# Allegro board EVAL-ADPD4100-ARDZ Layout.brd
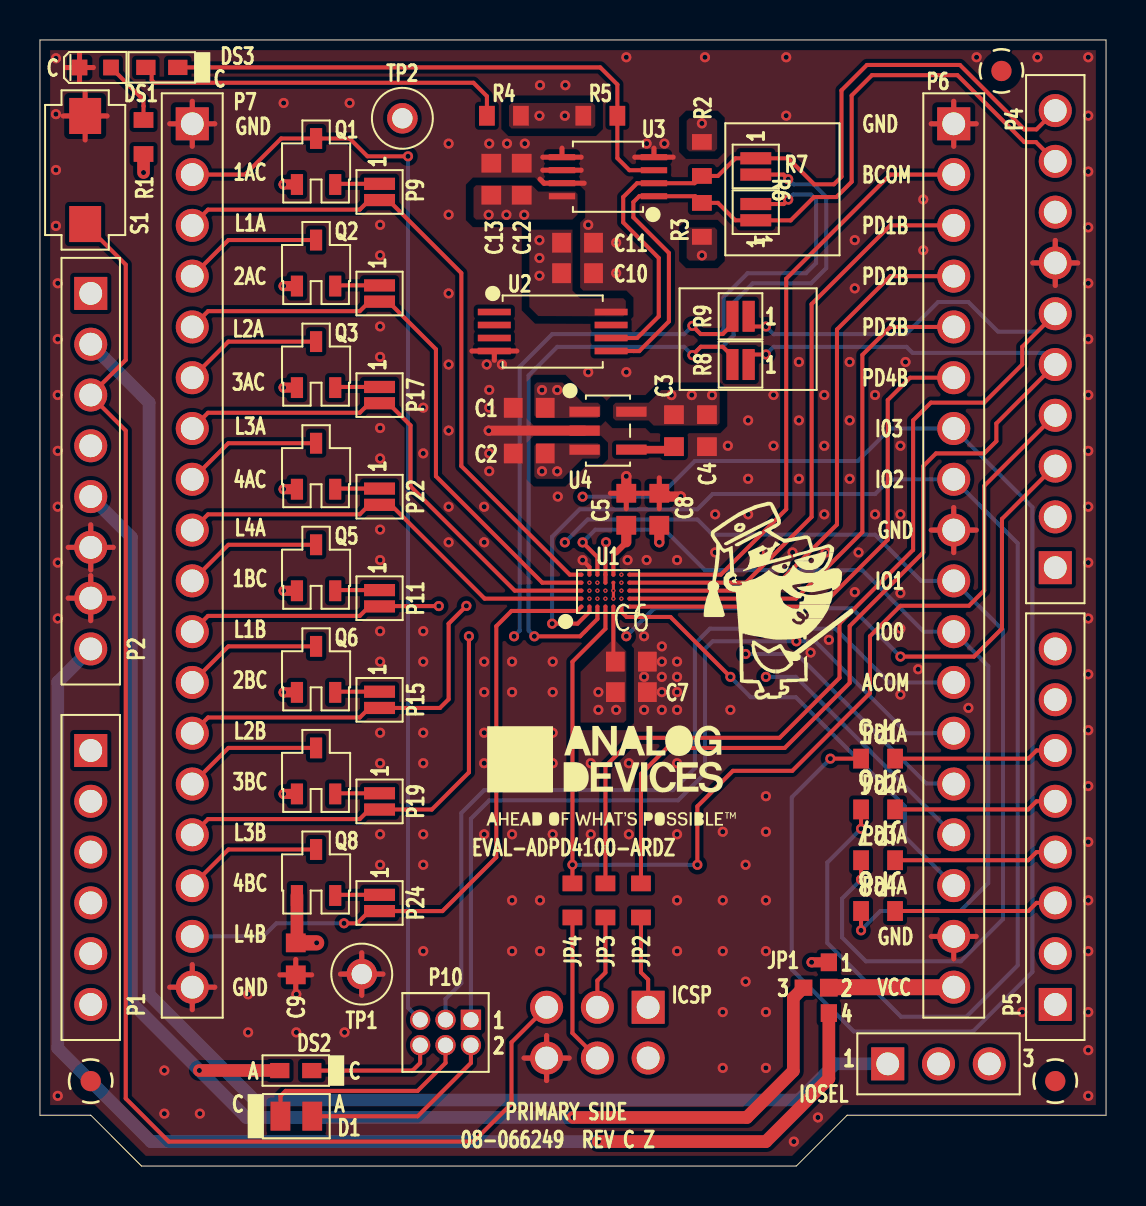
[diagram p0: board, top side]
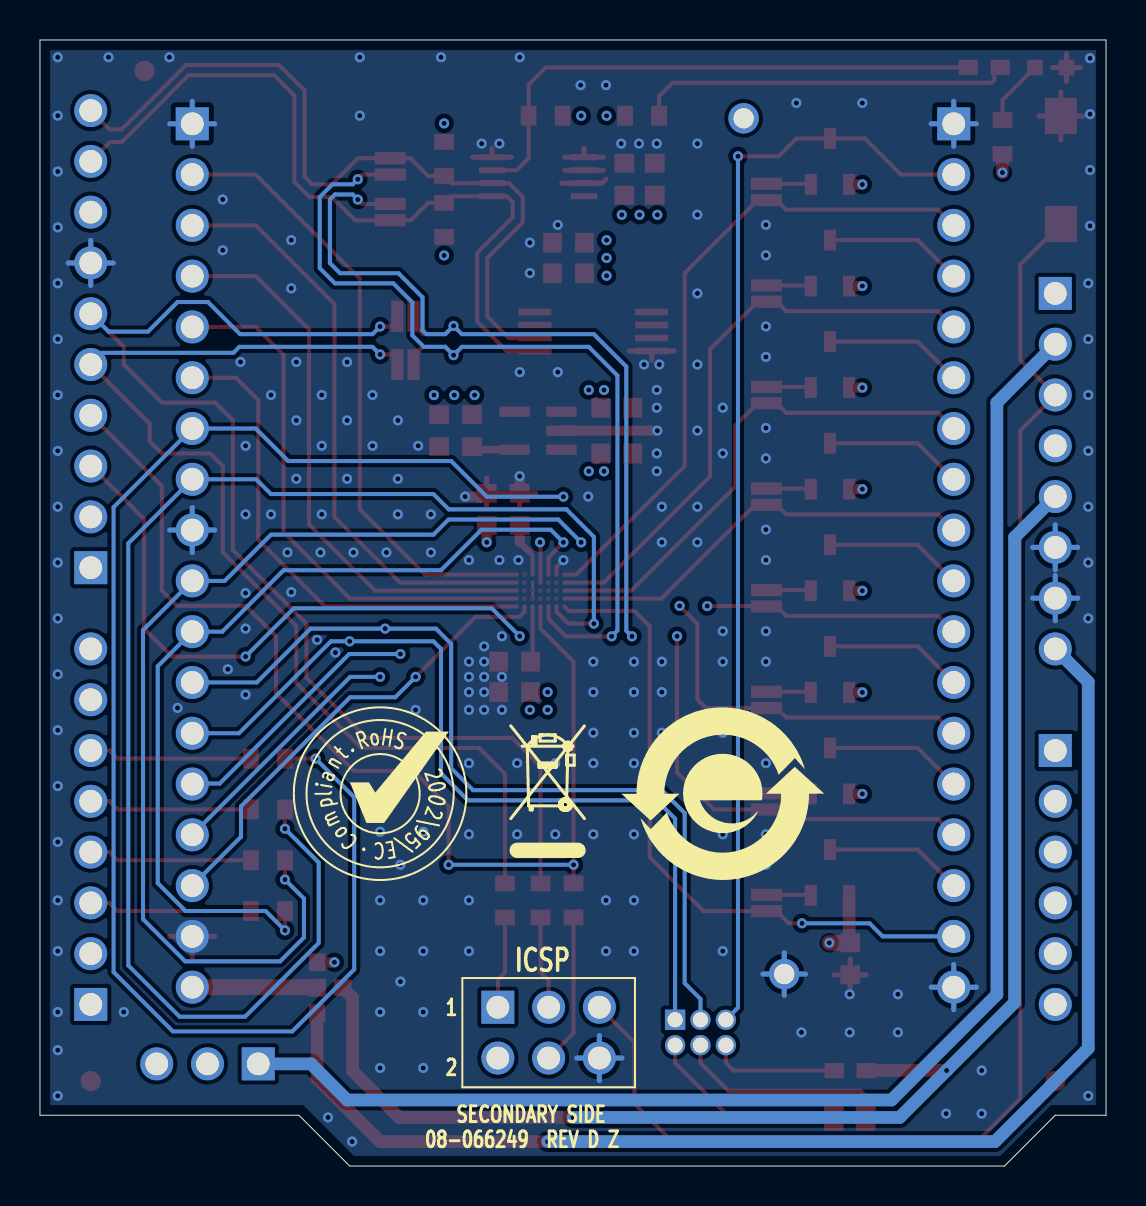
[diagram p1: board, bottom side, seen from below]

Outline 53.34 x 56.31 mm; copper layers: TOP, L2_GND, L3_PWR, BOTTOM. Coordinates in mm from the lower left corner of the outline.
Outline path: 0,56.31 0,2.54 2.54,2.54 5.08,0 37.85,0 40.39,2.54 53.34,2.54 53.34,56.31 0,56.31

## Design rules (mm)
constraint set DEFAULT: min track width 0.203

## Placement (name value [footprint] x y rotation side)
C1  0.1uF  [C0603]  24.48 37.92 180 top
C2  4.7uF  [C0603]  24.48 35.63 180 top
C3  0.01uF  [C0603]  31.72 36.78 90 top
C4  10uF  [C0603]  33.37 36.78 270 top
C5  1uF  [C0603]  29.34 32.84 90 top
C6  0.1uF  [C0603]  29.59 25.22 0 top
C7  4.7uF  [C0603]  29.59 23.7 0 top
C8  0.1uF  [C0603]  30.99 32.84 90 top
C9  4.7uF  [C0603]  12.8 10.36 270 top
C10  0.1uF  [C0603]  26.9 44.65 0 top
C11  4.7uF  [C0603]  26.9 46.17 0 top
C12  0.1uF  [C0603]  24.1 49.35 90 top
C13  4.7uF  [C0603]  22.58 49.35 90 top
D1  VEMD1060X01  [D0805_A]  12.83 2.49 0 top
DS1  SML-LX0603GW-TR  [LED0603-2]  2.77 54.94 0 top
DS2  TLMS1100-GS08  [LED0603]  12.8 4.77 180 top
DS3  TLMS1100-GS08  [LED0603]  6.1 54.94 180 top
IOSEL  TSW-103-08-T-S  [CNTHMHDR1X3L300W100H343]  42.42 5.11 0 top
JP1  4PIN_JUMPER  [4PINJUMPER_0402]  39.47 8.92 0 top
JP2  0  [R0603]  30.07 13.28 90 top
JP3  0  [R0603]  28.29 13.28 90 top
JP4  0  [R0603]  26.64 13.28 90 top
JP5  0  [R0603]  41.93 20.37 0 top
JP6  0  [R0603]  41.93 17.83 0 top
JP7  0  [R0603]  41.93 15.29 0 top
JP8  0  [R0603]  41.93 12.75 0 top
NOREF  -  []  0 2.54 0 top
NOREF#2  -  []  -47.84 -67.68 0 top
NOREF#3  -  []  0 56.31 0 top
NOREF#4  -  []  26.67 67.77 0 top
NOREF#5  -  []  94.36 104.39 0 top
NOREF#6  -  []  53.34 56.31 180 top
NOREF#7  -  []  0 56.31 0 top
NOREF#8  -  []  37.85 0 90 top
NOREF#9  -  []  53.34 2.54 90 top
NOREF#10  -  [unnamed#2]  2.54 4.24 0 top
NOREF#11  -  []  -35.58 -101.92 0 top
NOREF#12  -  []  0 56.31 270 top
NOREF#13  -  []  28.29 19.49 0 top
NOREF#14  -  []  2.54 43.64 270 top
NOREF#15  -  []  53.34 2.54 0 top
NOREF#16  -  [unnamed#2]  48.11 54.77 0 top
NOREF#17  -  []  0 2.54 0 top
NOREF#18  -  []  -25.68 -63.3 0 top
NOREF#19  -  []  44.24 305.7 0 top
NOREF#20  -  []  2.54 2.54 0 top
NOREF#21  -  [unnamed#2]  50.8 4.24 0 top
NOREF#22  -  []  40.39 2.54 0 top
NOREF#23  -  []  37.85 0 0 top
NOREF#24  -  []  -35.58 -101.92 0 top
NOREF#25  -  []  91.44 97.28 0 top
NOREF#26  -  []  5.08 0 0 top
NOREF#27  -  []  -35.58 -101.92 0 top
NOREF#28  -  []  -38.35 -57.07 0 top
NOREF#29  -  []  36.96 28.27 0 top
NOREF#30  -  []  -7.16 231.15 0 top
NOREF#31  -  []  28.14 15.47 180 bottom
NOREF#32  -  []  36.32 18.62 180 bottom
NOREF#33  -  []  19.18 18.62 180 bottom
P1  SSQ-106-03-T-S  [CNSAMTECSSQ-106-XX-X-S]  2.54 20.78 270 top
P2  SSQ-108-03-T-S  [CNSAMTECSSQ-108-XX-X-S]  2.54 43.64 270 top
P3  SSQ-103-03-T-D  [CNSAMTECSSQ-103-XX-X-D]  30.43 7.94 180 bottom
P4  SSQ-110-03-T-S  [CNSAMTECSSQ-110-XX-X-S]  50.8 29.92 90 top
P5  SSQ-108-03-T-S  [CNSAMTECSSQ-108-XX-X-S]  50.8 8.08 90 top
P6  TSW-118-16-G-S  [CNHDR1X18H420]  45.72 52.12 270 top
P7  TSW-118-16-G-S  [CNHDR1X18H420]  7.62 52.12 270 top
P9  -  [JPSLD02]  16.99 48.71 270 top
P10  FTS-103-01-F-D  [CNTHMHDR2X3L150W135H164]  21.56 7.31 180 top
P11  -  [JPSLD02]  16.99 28.39 270 top
P13  -  [JPSLD02]  16.99 43.63 270 top
P15  -  [JPSLD02]  16.99 23.31 270 top
P17  -  [JPSLD02]  16.99 38.55 270 top
P19  -  [JPSLD02]  16.99 18.23 270 top
P22  -  [JPSLD02]  16.99 33.47 270 top
P24  -  [JPSLD02]  16.99 13.15 270 top
Q1  MMBT2222A-TP  [SOT23_B]  13.82 50.24 0 top
Q2  MMBT2222A-TP  [SOT23_B]  13.82 45.16 0 top
Q3  MMBT2222A-TP  [SOT23_B]  13.82 40.08 0 top
Q4  MMBT2222A-TP  [SOT23_B]  13.82 35 0 top
Q5  MMBT2222A-TP  [SOT23_B]  13.82 29.92 0 top
Q6  MMBT2222A-TP  [SOT23_B]  13.82 24.84 0 top
Q7  MMBT2222A-TP  [SOT23_B]  13.82 19.76 0 top
Q8  MMBT2222A-TP  [SOT23_B]  13.82 14.68 0 top
R1  330  [R0603]  5.18 51.46 270 top
R2  10K  [R0603]  33.12 50.37 270 top
R3  10K  [R0603]  33.12 47.32 90 top
R4  330  [R0603]  23.21 52.52 0 top
R5  10K  [R0603]  28.04 52.52 0 top
R6  -  [JPSLD02]  35.81 47.7 90 top
R7  -  [JPSLD02]  35.81 49.99 270 top
R8  -  [JPSLD02]  35.05 40.08 180 top
R9  -  [JPSLD02]  35.05 42.5 180 top
S1  SKQMBBE010  [SWSML236W138H197]  2.26 49.81 270 top
TP1  WHT  [CNKEY5001TP]  16.1 9.6 0 top
TP2  WHT  [CNKEY5001TP]  18.13 52.4 0 top
U1  ADPD4100BCBZR7  [WLCSP35]  28.42 28.73 0 top
U2  M24C16-RDW6TP  [TSSOP8]  25.65 41.73 270 top
U3  ADT75BRMZ  [MSOP8]  28.42 49.48 90 top
U4  LT1761ES5-1.8#TRPBF  [TSOT-5]  28.42 36.78 270 top

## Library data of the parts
C1 C6 C8 C10 C12 = CAP: User Part Number: UPN; Tolerance: 10; alternate symbols: (C0603L); part number: CAP_SM-0.1UF,16V,10,E022365,C0603; tolerance: 10
C2 C7 C9 C11 C13 = CAP: User Part Number: UPN; Tolerance: 10; alternate symbols: (C0603L); part number: CAP_SM-4.7UF,25V,10,E035948,C0603; tolerance: 10
C3 = CAP: User Part Number: UPN; Tolerance: 10; alternate symbols: (C0603L); part number: CAP_SM-0.01UF,50V,10,E018587,C0603; tolerance: 10
C4 = CAP: User Part Number: UPN; Tolerance: 20; alternate symbols: (C0603L); part number: CAP_SM-10UF,10V,20,E022682,C0603; tolerance: 20
C5 = CAP: User Part Number: UPN; Tolerance: 10; alternate symbols: (C0603L); part number: CAP_SM-1UF,25V,10,E034292,C0603; tolerance: 10
D1 = DIOPHOTO: User Part Number: UPN; Tolerance: N/A; alternate symbols: (); part number: DIOPHOTO_SM-VEMD1060X01,20V,N/A,E049449,D0805_A; tolerance: N/A
DS1 = DIOLED: Tolerance: N/A; User Part Number: UPN; alternate symbols: (); part number: DIOLED_SM-SML-LX0603GW-TR,N/A,N/A,E018702,LED0603-2; tolerance: N/A
DS2 DS3 = DIOLED: Tolerance: N/A; User Part Number: UPN; alternate symbols: (); part number: DIOLED_SM-TLMS1100-GS08,N/A,N/A,E015386,LED0603; tolerance: N/A
IOSEL = CN3P: User Part Number: UPN; Tolerance: N/A; alternate symbols: (); part number: CN3P_TH-TSW-103-08-T-S,E031365,CNTHMHDR1X3L300W100H343; tolerance: N/A
JP1 = NC4P_JMPR: Tolerance: N/A; User Part Number: UPN; alternate symbols: (); part number: NC4P_JMPR_SM-4PIN_JUMPER,E006496,4PINJUMPER_0402; tolerance: N/A
JP2-JP8 = RESJMPRSHRT: User Part Number: UPN; Tolerance: JUMPER; alternate symbols: (R0603L); part number: RESJMPRSHRT_SM-0,E004447,1/10W,JUMPER,R0603; tolerance: JUMPER
P1 = CN6P: User Part Number: UPN; Tolerance: N/A; alternate symbols: (); part number: CN6P_TH-SSQ-106-03-T-S,E027150,CNSAMTECSSQ-106-XX-X-S; tolerance: N/A
P2 P5 = CN8P_A: User Part Number: UPN; Tolerance: N/A; alternate symbols: (); part number: CN8P_A_TH-SSQ-108-03-T-S,E027149,CNSAMTECSSQ-108-XX-X-S; tolerance: N/A
P3 = CN6P: User Part Number: UPN; Tolerance: N/A; alternate symbols: (); part number: CN6P_TH-SSQ-103-03-T-D,E027152,CNSAMTECSSQ-103-XX-X-D; tolerance: N/A
P4 = CN10P: User Part Number: UPN; Tolerance: N/A; alternate symbols: (); part number: CN10P_TH-SSQ-110-03-T-S,E027151,CNSAMTECSSQ-110-XX-X-S; tolerance: N/A
P6 P7 = CN18P: User Part Number: UPN; Tolerance: N/A; alternate symbols: (); part number: CN18P_TH-TSW-118-16-G-S,E017097,CNHDR1X18H420; tolerance: N/A
P9 P11 P13 P15 P17 P19 P22 P24 R6-R9 = NC2P: User Part Number: UPN; Tolerance: N/A; alternate symbols: (); part number: NC2P_SM-JPSLD02,E006230,JPSLD02; tolerance: N/A
P10 = CN6P_ODD_EVEN: User Part Number: UPN; Tolerance: N/A; alternate symbols: (); part number: CN6P_ODD_EVEN_TH-FTS-103-01-F-D,E047281,CNTHMHDR2X3L150W135H164; tolerance: N/A
Q1-Q8 = TRANNPN_V2: User Part Number: UPN; Tolerance: N/A; alternate symbols: (); part number: TRANNPN_V2_SM-MMBT2222A-TP,E035724,SOT23_B; tolerance: N/A
R1 R4 = RES: User Part Number: UPN; Tolerance: 5; alternate symbols: (R0603L); part number: RES_SM-330,E003857,1/10W,5,R0603; tolerance: 5
R2 R3 R5 = RES: User Part Number: UPN; Tolerance: 5; alternate symbols: (R0603L); part number: RES_SM-10K,E042780,1/10W,5,R0603; tolerance: 5
S1 = SWSPST2PIN_V3: Tolerance: N/A; User Part Number: UPN; alternate symbols: (); part number: SWSPST2PIN_V3_SM-SKQMBBE010,E026439,SWSML236W138H197; tolerance: N/A
TP1 TP2 = CNTP1P: Tolerance: N/A; User Part Number: UPN; alternate symbols: (); part number: CNTP1P_TH-WHT,E006153,CNKEY5001TP; tolerance: N/A
U1 = ADPD4100: Tolerance: N/A; User Part Number: UPN; alternate symbols: (); part number: ADPD4100_SM-ADPD4100BCBZR7,E041910,WLCSP35; tolerance: N/A
U2 = ICM24CXX_V2: Tolerance: N/A; User Part Number: UPN; alternate symbols: (); part number: ICM24CXX_V2_SM-M24C16-RDW6TP,E026352,TSSOP8; tolerance: N/A
U3 = ADT75: Tolerance: N/A; User Part Number: UPN; alternate symbols: (); part number: ADT75_SM-ADT75BRMZ,E029518,MSOP8; tolerance: N/A
U4 = LINLT1761_X: User Part Number: UPN; Tolerance: N/A; alternate symbols: (); part number: LINLT1761_X_SM-LT1761ES5-1.8#TRPBF,E015635,TSOT-5; tolerance: N/A

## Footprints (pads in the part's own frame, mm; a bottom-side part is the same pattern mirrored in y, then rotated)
4PINJUMPER_0402
  rect 0.813x0.889 smd: 1(0,1.27) 4(0,-1.27)
  rect 0.889x0.889 smd: 2(0,0)
  rect 0.889x0.813 smd: 3(-1.27,0)
C0603
  rect 0.94x0.991 smd: 1(-0.8,0) 2(0.8,0)
CNHDR1X18H420
  rect 1.651x1.651 hole 1.143: 1(0,0)
  round 1.651 hole 1.143: 2(2.54,0) 3(5.08,0) 4(7.62,0) 5(10.16,0) 6(12.7,0) 7(15.24,0) 8(17.78,0) 9(20.32,0) 10(22.86,0) 11(25.4,0) 12(27.94,0) 13(30.48,0) 14(33.02,0) 15(35.56,0) 16(38.1,0) 17(40.64,0) 18(43.18,0)
CNKEY5001TP
  round 1.524 hole 1.016: 1(0,0)
CNSAMTECSSQ-103-XX-X-D
  rect 1.651x1.651 hole 1.143: 1(0,0)
  round 1.651 hole 1.143: 2(0,-2.54) 3(2.54,0) 4(2.54,-2.54) 5(5.08,0) 6(5.08,-2.54)
CNSAMTECSSQ-106-XX-X-S
  rect 1.651x1.651 hole 1.143: 1(0,0)
  round 1.651 hole 1.143: 2(2.54,0) 3(5.08,0) 4(7.62,0) 5(10.16,0) 6(12.7,0)
CNSAMTECSSQ-108-XX-X-S
  rect 1.651x1.651 hole 1.143: 1(0,0)
  round 1.651 hole 1.143: 2(2.54,0) 3(5.08,0) 4(7.62,0) 5(10.16,0) 6(12.7,0) 7(15.24,0) 8(17.78,0)
CNSAMTECSSQ-110-XX-X-S
  rect 1.651x1.651 hole 1.143: 1(0,0)
  round 1.651 hole 1.143: 2(2.54,0) 3(5.08,0) 4(7.62,0) 5(10.16,0) 6(12.7,0) 7(15.24,0) 8(17.78,0) 9(20.32,0) 10(22.86,0)
CNTHMHDR1X3L300W100H343
  rect 1.651x1.651 hole 1.143: 1(0,0)
  round 1.651 hole 1.143: 2(2.54,0) 3(5.08,0)
CNTHMHDR2X3L150W135H164
  rect 1.016x1.016 hole 0.762: 1(0,0)
  round 1.016 hole 0.762: 2(0,1.27) 3(1.27,0) 4(1.27,1.27) 5(2.54,0) 6(2.54,1.27)
D0805_A
  rect 0.991x1.448 smd: A(0.795,0) C(-0.795,0)
JPSLD02
  rect 0.61x1.549 smd: 1(-0.406,0) 2(0.406,0)
LED0603
  rect 0.965x0.762 smd: A(0.8,0) C(-0.8,0)
LED0603-2
  rect 0.787x0.787 smd: A(0.787,0) C(-0.787,0)
MSOP8
  rect 0.305x1.321 smd: 1(-0.975,-2.301) 2(-0.325,-2.301) 3(0.325,-2.301) 4(0.975,-2.301) 5(0.975,2.301) 6(0.325,2.301) 7(-0.325,2.301) 8(-0.975,2.301)
R0603
  rect 0.787x0.991 smd: 1(-0.851,0) 2(0.851,0)
SOT23_B
  rect 0.61x1.041 smd: 1(-0.958,-1.15) 2(0.958,-1.15) 3(0,1.15)
SWSML236W138H197
  rect 1.803x1.6 smd: 1(-2.703,0) 2(2.703,0)
TSOT-5
  rect 0.508x1.524 smd: 1(-0.95,-1.171) 2(0,-1.171) 3(0.95,-1.171) 4(0.95,1.171) 5(-0.95,1.171)
TSSOP8
  rect 0.33x1.651 smd: 1(-0.975,-2.921) 2(-0.325,-2.921) 3(0.325,-2.921) 4(0.975,-2.921) 5(0.975,2.921) 6(0.325,2.921) 7(-0.325,2.921) 8(-0.975,2.921)
unnamed#2
  round 1.016 smd: (0,0)
WLCSP35
  round 0.203 smd: A1(-1.331,-0.754) A2(-1.331,-0.356) A3(-1.331,0.046) A4(-1.331,0.445) A5(-1.331,0.846) B1(-0.93,-0.754) B2(-0.93,-0.356) B3(-0.93,0.046) B4(-0.93,0.445) B5(-0.93,0.846) C1(-0.531,-0.754) C2(-0.531,-0.356) C3(-0.531,0.046) C4(-0.531,0.445) C5(-0.531,0.846) D1(-0.13,-0.754) D2(-0.13,-0.356) D3(-0.13,0.046) D4(-0.13,0.445) D5(-0.13,0.846) E1(0.269,-0.754) E2(0.269,-0.356) E3(0.269,0.046) E4(0.269,0.445) E5(0.269,0.846) F1(0.671,-0.754) F2(0.671,-0.356) F3(0.671,0.046) F4(0.671,0.445) F5(0.671,0.846) G1(1.069,-0.754) G2(1.069,-0.356) G3(1.069,0.046) G4(1.069,0.445) G5(1.069,0.846)

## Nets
1V8D: C3.2(N2) C4.1 C6.1 C7.1 C9.1 IOSEL.3(N3) Q1.1 Q2.1 Q3.1 Q4.1 Q5.1 Q6.1 Q7.1 Q8.1 TP2.1(N1) U1.D4 U1.D5 U1.E1 U4.5
3V_ARD: C1.1 C2.1 JP1.1 P2.4 P3.2 R1.2(N2) U4.1 U4.3(SHDN_N)
5V_ARD: DS2.A(P) JP1.3 P2.5
DGND: C1.2(N2) C2.2(N2) C4.2(N2) C5.2(N2) C6.2(N2) C7.2(N2) C8.2(N2) C9.2(N2) C10.2(N2) C11.2(N2) C12.2(N2) C13.2(N2) DS1.C P2.6 P2.7 P3.6(N6) P4.7 P6.1 P6.9(N9) P6.17 P7.1 P7.18 S1.1 TP1.1(N1) U1.B5 U1.E2 U1.E3 U1.E4 U2.4 U3.4 U3.5 U3.6 U3.7 U4.2
VCC_LED: JP1.2(COM) P6.18
ACOM: P6.12 P10.3 U1.F5
ADPD_GPIO0: JP8.1 P6.11 U1.C5
ADPD_GPIO1: JP7.1 P6.10 U1.C4
ADPD_GPIO2: JP6.1 P6.8 U1.B1
ADPD_GPIO3: JP5.1 P6.7 U1.C3
ARD_CS: P4.3 U1.D2
ARD_MISO: JP2.2(S2) P4.5 R8.1
ARD_MOSI: JP4.2(S2) P4.4 U1.D1
ARD_SCK: JP3.2(S2) P4.6 R9.1
ARD_SCL: P4.10 R2.2(N2) R7.1 U2.6 U3.2
ARD_SDA: P4.9(N9) R3.2(N2) R6.1 U2.5 U3.1
BCOM: P6.2 U1.G5
EXT_VIN: JP1.4 P2.8(N8)
IOREF: IOSEL.1 P2.2
IOVDD: C8.1 C10.1 C11.1 C12.1 C13.1 IOSEL.2 R2.1 R3.1 R4.2(N2) R5.1 U1.D3 U2.8 U3.8(VDD)
LD1A_CAT: P7.2 P10.5 Q1.3
LD1B_CAT: P7.10 Q5.3
LD2A_CAT: P7.4 Q2.3
LD2B_CAT: P7.12 Q6.3
LD3A_CAT: P7.6 Q3.3
LD3B_CAT: P7.14 Q7.3
LD4A_CAT: P7.8 Q4.3
LD4B_CAT: P7.16 Q8.3
LED1A: P7.3 P9.2(N2) U1.A5
LED1B: P7.11 P11.2(N2) U1.B4
LED2A: P7.5 P13.2(N2) U1.A4
LED2B: P7.13 P15.2(N2) U1.B3
LED3A: P7.7 P17.2(N2) U1.A3
LED3B: P7.15 P19.2(N2) U1.B2
LED4A: P7.9(N9) P22.2(N2) U1.A2
LED4B: P7.17 P24.2(N2) U1.A1
MISO: JP2.1 P3.1
MOSI: JP4.1 P3.4
PD1A: P6.13 P10.1 U1.F4
PD1B: P6.3 U1.G4
PD2A: P6.14 U1.F3
PD2B: P6.4 U1.G3
PD3A: P6.15 U1.F2
PD3B: P6.5 U1.G2
PD4A: P6.16 U1.F1
PD4B: P6.6 U1.G1
RESET: P2.3 P3.5 S1.2(B)
SCK: JP3.1 P3.3
SPIMISO/I2CSCL: R7.2(N2) R8.2(N2) U1.C1
SPISCK/I2CSDA: R6.2(N2) R9.2(N2) U1.C2
UNNAMED_2_ADPD4100_I288_VREF: C5.1 U1.E5(VREF)
UNNAMED_2_ADT75_I175_OS: DS3.C R5.2(N2) U3.3
UNNAMED_2_CAP_I46_N1: C3.1 U4.4
UNNAMED_2_CN6PODDEVEN_I283_N2: D1.A(P) P10.2
UNNAMED_2_CN6PODDEVEN_I283_N4: D1.C P10.4
UNNAMED_2_CN6PODDEVEN_I283_N6: DS2.C P10.6(N6)
UNNAMED_2_CN8PA_I159_N3: JP8.2(S2) P5.3
UNNAMED_2_CN8PA_I159_N4: JP7.2(S2) P5.4
UNNAMED_2_CN8PA_I159_N5: JP6.2(S2) P5.5
UNNAMED_2_CN8PA_I159_N6: JP5.2(S2) P5.6
UNNAMED_2_DIOLED_I100_P: DS1.A(P) R1.1
UNNAMED_2_DIOLED_I182_P: DS3.A(P) R4.1
UNNAMED_2_NC2P_I236_N1: P24.1 Q8.2(E)
UNNAMED_2_NC2P_I275_N1: P9.1 Q1.2(E)
UNNAMED_2_NC2P_I276_N1: P13.1 Q2.2(E)
UNNAMED_2_NC2P_I277_N1: P17.1 Q3.2(E)
UNNAMED_2_NC2P_I278_N1: P22.1 Q4.2(E)
UNNAMED_2_NC2P_I279_N1: P11.1 Q5.2(E)
UNNAMED_2_NC2P_I280_N1: P15.1 Q6.2(E)
UNNAMED_2_NC2P_I281_N1: P19.1 Q7.2(E)

Pads without a net: P1 1 2 3 4 5 6; P2 1; P4 1 2 8; P5 1 2 7 8; U2 1 2 3 7

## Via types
v1: diameter 0.508, hole 0.254, TOP to BOTTOM, 265 vias
v2: diameter 0.203, hole 0.102, TOP to L2_GND, 14 vias

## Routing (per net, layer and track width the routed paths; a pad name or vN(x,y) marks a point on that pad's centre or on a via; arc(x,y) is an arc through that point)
1V8D: length 17.2
  TOP w0.203: v1(28.32,31.19) 28.29,31.17 U1.D5 U1.D4 ; C6.1 28.69,25.32 U1.E1
  TOP w0.508: Q2.1 v1(12.19,44.01) ; Q4.1 v1(12.19,33.85) ; Q6.1 v1(12.19,23.69) ; Q5.1 v1(12.19,28.77) ; Q1.1 v1(12.19,49.09) ; Q7.1 v1(12.19,18.61) ; Q3.1 v1(12.19,38.93)
  TOP w0.635: C9.1 12.86,11.22 Q8.1
  TOP w0.762: v1(13.84,11.16) C9.1
  L3_PWR w0.254: 18.13,51.34 TP2.1 ; TP2.1 18.13,53.46 ; TP2.1 19.2,52.4 ; TP2.1 17.07,52.4
  vias: v1(27.94,23.7) v1(27.94,22.81) v1(28.83,22.81) v1(31.6,38.55) v1(32.61,38.55) v1(33.63,38.55)
3V_ARD: length 9.7
  TOP w0.508: v1(38.61,10.19) JP1.1
  TOP w0.635: R1.2 v1(5.18,49.69)
  L3_PWR w0.254: P2.4 3.67,36.02 ; P2.4 2.54,34.89 ; P2.4 2.54,37.15 ; P3.2 30.43,6.53 ; P3.2 30.43,4.27 ; P3.2 31.56,5.4 ; P3.2 29.3,5.4
  vias: v1(25.12,38.81) v1(25.12,34.74) v1(25.88,38.81) v1(25.88,34.74)
5V_ARD: length 71
  TOP w0.635: JP1.3 37.69,8.41 37.69,4.75 35.37,2.43 v1(26.67,2.43) ; DS2.A 11.99,4.78 v1(7.98,4.78)
  BOTTOM w0.635: v1(26.67,2.43) 10.33,2.43 v1(7.98,4.78) 4.57,8.18 4.57,31.45 P2.5
DGND: length 166.3
  TOP w0.152: v2(28.69,28.37) v2(28.69,28.78) U1.E4
  TOP w0.203: v1(27.15,30.3) 27.49,29.96 U1.B5
  TOP w0.254: 6.49,8.94 P7.18 ; P7.18 7.62,7.82 ; P7.18 7.62,10.07 ; P7.18 8.75,8.94 ; U3.5 27.08,50.45 ; U3.5 25.16,50.45 ; U3.5 26.12,50.9 ; 15.04,9.6 TP1.1 ; TP1.1 17.16,9.6 ; TP1.1 16.1,8.54 ; TP1.1 16.1,10.66 ; 22.73,40.29 U2.4 ; U2.4 23.86,40.76 ; U2.4 21.61,40.76 ; 29.34,32.87 C5.2 ; C5.2 30.13,33.65 ; C5.2 28.54,33.65 ; 49.67,45.16 P4.7 ; P4.7 51.93,45.16 ; P4.7 50.8,46.29 ; P4.7 50.8,44.04 ; 44.59,52.12 P6.1 ; P6.1 45.72,53.25 ; P6.1 45.72,51 ; P6.1 46.85,52.12 ; DS1.C 1.98,55.63 ; DS1.C 2.67,54.94 ; DS1.C 1.28,54.94 ; DS1.C 1.98,54.24 ; S1.1 3.36,52.51 ; S1.1 1.16,52.51 ; S1.1 2.26,53.72 ; S1.1 2.26,51.31 ; P2.7 3.67,28.4 ; P2.7 2.54,27.27 ; P2.7 2.54,29.53 ; P2.7 1.41,28.4 ; 2.54,29.81 P2.6 ; P2.6 2.54,32.07 ; P2.6 1.41,30.94 ; P2.6 3.67,30.94 ; U3.4 31.68,50.45 ; U3.4 29.76,50.45 ; U3.4 30.72,50.9 ; P6.9 46.85,31.8 ; P6.9 44.59,31.8 ; P6.9 45.72,32.93 ; P6.9 45.72,30.68 ; P7.1 8.75,52.12 ; P7.1 6.49,52.12 ; P7.1 7.62,51 ; P7.1 7.62,53.25 ; C9.2 13.59,9.56 ; C9.2 12,9.56 ; C9.2 12.8,10.33 ; C9.2 12.8,8.79 ; 25.35,4.27 P3.6 ; P3.6 26.48,5.4 ; P3.6 24.22,5.4 ; P3.6 25.35,6.53 ; 27.23,49.15 U3.7 25.22,49.15 25.02,49.35 ; 45.72,10.36 P6.17 ; P6.17 44.59,11.48 ; P6.17 46.85,11.48 ; 30.19,33.65 C8.2 ; C8.2 30.99,34.42 ; C8.2 30.99,32.87 ; 25.16,49.8 U3.6 27.08,49.8
  TOP w0.5: U4.2 v1(22.45,36.78)
  TOP w0.508: 32.06,33.47 v1(32.07,33.48) 31.41,33.48 31.24,33.65 C8.2 ; C5.2 v1(29.34,34.5)
  L2_GND w0.127: v1(29.4,30.3) 28.8,29.7 28.8,28.88 28.7,28.78 v2(28.69,28.78)
  L2_GND w0.178: v2(28.69,28.78) v2(28.69,28.37)
  L2_GND w0.254: P4.7 51.93,45.16 ; P4.7 50.8,44.04 ; P4.7 49.67,45.16 ; P4.7 50.8,46.29 ; 44.59,31.8 P6.9 ; P6.9 46.85,31.8 ; P6.9 45.72,30.68 ; P6.9 45.72,32.93 ; 45.72,10.36 P6.17 ; P6.17 45.72,12.61 ; P6.17 44.59,11.48 ; P6.17 46.85,11.48 ; P7.18 8.75,8.94 ; P7.18 6.49,8.94 ; P7.18 7.62,7.82 ; P7.18 7.62,10.07 ; P2.6 2.54,32.07 ; P2.6 2.54,29.81 ; P2.6 1.41,30.94 ; P2.6 3.67,30.94 ; P6.1 45.72,53.25 ; P6.1 46.85,52.12 ; P6.1 45.72,51 ; P6.1 44.59,52.12 ; TP1.1 17.16,9.6 ; TP1.1 16.1,8.54 ; TP1.1 15.04,9.6 ; TP1.1 16.1,10.66 ; 7.62,51 P7.1 ; P7.1 8.75,52.12 ; P7.1 6.49,52.12 ; P7.1 7.62,53.25 ; 25.35,4.27 P3.6 ; P3.6 26.48,5.4 ; P3.6 24.22,5.4 ; P3.6 25.35,6.53 ; 2.54,27.27 P2.7 ; P2.7 1.41,28.4 ; P2.7 2.54,29.53 ; P2.7 3.67,28.4
  BOTTOM w0.254: P3.6 26.48,5.4 ; P3.6 24.22,5.4 ; P3.6 25.35,6.53 ; P3.6 25.35,4.27 ; 44.59,31.8 P6.9 ; P6.9 46.85,31.8 ; P6.9 45.72,32.93 ; P6.9 45.72,30.68 ; P6.1 46.85,52.12 ; P6.1 45.72,53.25 ; P6.1 45.72,51 ; P6.1 44.59,52.12 ; P2.6 2.54,32.07 ; P2.6 1.41,30.94 ; P2.6 3.67,30.94 ; P2.6 2.54,29.81 ; 6.49,52.12 P7.1 ; P7.1 8.75,52.12 ; P7.1 7.62,53.25 ; P7.1 7.62,51 ; 15.04,9.6 TP1.1 ; TP1.1 16.1,8.54 ; TP1.1 17.16,9.6 ; TP1.1 16.1,10.66 ; 7.62,7.82 P7.18 ; P7.18 6.49,8.94 ; P7.18 7.62,10.07 ; P7.18 8.75,8.94 ; P2.7 2.54,29.53 ; P2.7 3.67,28.4 ; P2.7 2.54,27.27 ; P2.7 1.41,28.4 ; 49.67,45.16 P4.7 ; P4.7 50.8,46.29 ; P4.7 50.8,44.04 ; P4.7 51.93,45.16
  vias: v1(0.8,55.4) v1(0.8,52.61) v1(0.8,49.81) v1(0.8,47.02) v1(0.89,44.15) v1(0.89,41.35) v1(0.89,38.56) v1(0.89,35.77) v1(0.89,32.97) v1(0.89,30.18) v1(0.89,27.38) v1(0.89,3.51) v1(6.22,4.78) v1(6.22,2.62) v1(8,2.62) v1(10.41,8.59) v1(10.41,6.68) v1(12.19,53.16) v1(12.83,8.59) v1(12.83,6.68) v1(15.24,6.68) v1(15.49,53.16) v1(17.02,47.07) v1(17.02,45.54) v1(17.02,41.99) v1(17.02,40.46) v1(17.02,36.91) v1(17.02,35.38) v1(17.02,31.83) v1(17.02,30.3) v1(17.02,26.75) v1(17.02,25.22) v1(17.02,21.67) v1(17.02,20.14) v1(17.02,16.59) v1(17.02,15.06) v1(19.18,37.92) v1(19.18,35.64) v1(19.18,26.75) v1(19.18,25.22) v1(19.18,21.67) v1(19.18,20.14) v1(19.18,16.59) v1(19.18,15.06) v1(19.18,10.75) v1(20.45,51.13) v1(20.45,47.58) v1(20.45,43.64) v1(20.45,40.08) v1(20.45,36.78) v1(20.45,32.97) v1(20.45,31.19) v1(22.23,32.97) v1(22.23,31.19) v1(22.23,25.22) v1(22.23,23.7) v1(22.23,21.67) v1(22.23,20.14) v1(22.23,16.59) v1(22.35,40.08) v1(22.48,51.13) v1(22.48,38.81) v1(22.48,37.92) v1(22.48,35.64) v1(22.48,34.75) v1(23.11,40.08) v1(23.37,51.13) v1(23.62,25.22) v1(23.62,23.7) v1(23.62,21.67) v1(23.62,20.14) v1(23.62,16.59) v1(23.62,13.29) v1(23.62,10.75) v1(24.26,51.13) v1(25.02,54.05) v1(25.02,13.29) v1(25.02,10.75) v1(25.65,25.22) v1(25.65,23.7) v1(25.65,21.67) v1(25.65,20.14) v1(25.65,16.59) v1(25.91,33.48) v1(26.29,54.05) v1(27.43,47.07) v1(27.43,39.7) v1(27.56,20.14) v1(27.56,16.59) v1(28.83,46.18) v1(28.83,44.66) v1(29.34,55.45) v1(29.34,39.7) v1(29.46,20.14) v1(29.46,16.59) v1(30.23,26.49) v1(30.23,24.46) v1(30.23,22.81) v1(30.35,51.13) v1(30.35,30.3) v1(31.11,25.99) v1(31.11,25.22) v1(31.11,24.46) v1(31.11,23.7) v1(31.11,22.81) v1(31.24,51.13) v1(31.88,30.3) v1(31.88,25.22) v1(31.88,24.46) v1(31.88,23.7) v1(31.88,22.81) v1(31.88,20.14) v1(31.88,16.59) v1(31.88,13.29) v1(31.88,10.75) v1(33.27,55.45) v1(33.78,32.59) v1(33.78,30.69) v1(34.16,16.72) v1(34.16,13.29) v1(34.16,10.75) v1(34.16,7.7) v1(34.16,4.9) v1(34.42,36.02) v1(34.54,22.81) v1(35.31,15.06) v1(35.31,9.22) v1(35.43,37.29) v1(35.43,34.37) v1(35.43,32.59) v1(36,30.69) v1(36.32,18.49) v1(36.32,16.72) v1(36.32,13.29) v1(36.32,10.75) v1(36.32,7.7) v1(36.32,4.9) v1(36.7,38.56) v1(36.7,36.02) v1(37.34,55.45) v1(37.34,52.53) v1(37.66,30.69) v1(37.72,1.22) v1(37.97,40.21) v1(37.97,37.29) v1(37.97,34.37) v1(38.56,25.68) v1(38.93,2.43) v1(39.24,38.56) v1(39.24,36.02) v1(39.24,32.59) v1(39.31,30.69) v1(39.47,26.31) v1(40.51,40.21) v1(40.51,37.29) v1(40.51,34.37) v1(40.77,46.31) v1(40.77,43.89) v1(40.77,28.7) v1(40.96,30.69) v1(41.78,38.56) v1(41.78,32.59) v1(43.05,36.02) v1(43.05,32.59) v1(43.05,28.65) v1(43.05,26.88) v1(43.05,23.57) v1(43.31,40.21) v1(43.94,24.84) v1(44.2,48.34) v1(44.2,45.8) v1(46.46,22.91) v1(46.86,55.45) v1(49.15,7.7) v1(49.91,55.45) v1(52.45,55.45) v1(52.45,52.53) v1(52.45,49.74) v1(52.45,46.94) v1(52.45,44.15) v1(52.45,41.35) v1(52.45,38.56) v1(52.45,35.77) v1(52.45,32.97) v1(52.45,30.18) v1(52.45,27.38) v1(52.45,24.59) v1(52.45,21.8) v1(52.45,19) v1(52.45,16.21) v1(52.45,13.29) v1(52.45,10.75) v1(52.45,7.7) v1(52.45,5.79) v1(52.45,3.51)
VCC_LED: length 6.3
  TOP w0.8: P6.18 39.5,8.94 JP1.2
ACOM: length 52
  L2_GND w0.127: 30.54,29.35 29.49,29.35 29.27,29.58 v2(29.09,29.58)
  L2_GND w0.203: 30.54,29.35 33.08,29.35 35.56,26.88 v1(36.07,26.88)
  BOTTOM w0.203: P10.3 20.29,8.35 21.08,9.14 21.08,17.65 22.23,18.8 31.67,18.8 32.77,19.89 32.77,26.11 33.53,26.88 v1(36.07,26.88) 39.8,26.88 42.49,24.18 P6.12
ADPD_GPIO0: length 44.5
  TOP w0.203: U1.C5 27.89,30.45 v1(27.15,31.19) ; JP8.1 v1(41.08,11.79)
  BOTTOM w0.203: v1(27.15,31.19) 27.79,31.82 31.25,31.82 33.27,29.8 41.15,29.8 44.22,26.72 P6.11 47.45,25 47.45,14.15 46.05,12.75 42.05,12.75 v1(41.08,11.79)
ADPD_GPIO1: length 56
  TOP w0.203: JP7.1 v1(41.08,14.33)
  L2_GND w0.127: 27.4,29.66 v2(27.89,29.17)
  L2_GND w0.203: 27.4,29.66 26.64,29.66 26.26,30.05 v1(26.26,31.19)
  BOTTOM w0.203: v1(26.26,31.19) 27.4,32.33 32.9,32.33 33.66,31.57 41.78,31.57 44.09,29.26 P6.10 48.18,26.8 48.18,12.34 46.08,10.24 41.33,10.24 40.13,11.43 40.13,13.38 v1(41.08,14.33)
ADPD_GPIO2: length 73.1
  TOP w0.203: JP6.1 v1(41.08,16.87) ; U1.B1 27.49,27.72 26.9,27.12 v1(25.63,27.12)
  BOTTOM w0.203: v1(41.08,16.87) 39.4,15.18 39.4,11.15 43.08,7.47 46.35,7.47 48.92,10.03 48.92,31.14 P6.8 42.52,34.34 41.78,33.61 33.66,33.61 32.89,32.84 27,32.84 25.63,31.47 v1(25.63,27.12)
ADPD_GPIO3: length 81.5
  TOP w0.203: JP5.1 v1(39.55,20.37)
  L2_GND w0.127: 28.17,29.95 28.17,29.05 27.89,28.78 v2(27.89,28.78)
  L2_GND w0.203: 28.17,29.95 27.79,30.33 27.79,32.84 v1(27.15,33.47)
  BOTTOM w0.203: v1(39.55,20.37) 37.62,18.44 37.62,9.83 40.72,6.73 46.69,6.73 49.66,9.7 49.66,32.95 P6.7 42.55,36.88 40.92,35.26 32.77,35.26 30.98,33.47 v1(27.15,33.47)
ARD_CS: length 32.5
  TOP w0.203: v1(43.05,25.48) 46.74,25.48 48.13,26.88 48.13,32.36 50.78,35 P4.3
  L2_GND w0.127: 28.54,27.29 28.29,27.54 v2(28.29,28.37)
  L2_GND w0.203: 28.54,27.29 v1(29.34,26.49)
  BOTTOM w0.203: v1(43.05,25.48) 40.64,27.89 30.73,27.89 v1(29.34,26.49)
ARD_MISO: length 55.6
  TOP w0.203: JP2.2 30.07,19.61 31.37,20.91 37.26,20.91 40.51,24.16 40.51,27 44.2,30.69 44.2,35 44.83,35.64 47.24,35.64 47.85,36.25 47.85,37.14 P4.5 ; v1(36.32,40.59) 35.68,40.59 35.46,40.36 R8.1
  BOTTOM w0.203: v1(36.32,40.59) 36.7,40.97 43.36,40.97 43.66,40.67 50.22,40.67 P4.5
ARD_MOSI: length 54.4
  TOP w0.203: v1(32.89,15.06) 32.89,17.99 34.67,19.76 37.64,19.76 41.53,23.65 41.53,26.49 43.05,28.02 46.48,28.02 47.24,28.78 47.24,34.01 50.78,37.54 P4.4 ; U1.D1 28.29,26.87 26.64,25.22 v1(26.64,15.06) JP4.2
  BOTTOM w0.203: v1(26.64,15.06) v1(32.89,15.06)
ARD_SCK: length 61.2
  TOP w0.203: v1(36.32,41.98) 35.69,41.98 35.46,42.22 R9.1 ; JP3.2 28.29,19.99 29.72,21.41 37.01,21.41 40.01,24.41 40.01,27.13 43.69,30.81 43.69,37.29 44.58,38.18 47.24,38.18 49.15,40.08 49.15,40.97 P4.6
  BOTTOM w0.203: P4.6 49.91,41.73 47.93,41.73 46.46,43.21 44.93,43.21 43.33,41.6 36.7,41.6 v1(36.32,41.98)
ARD_SCL: length 39.2
  TOP w0.203: U2.6 29.88,41.41 30.96,42.49 30.96,45.41 29.18,47.19 29.18,48.46 29.87,49.15 U3.2 32.76,49.15 R2.2 33.92,49.52 34.8,50.4 R7.1 37.44,50.4 38.74,49.1 39.72,49.1 40.1,49.48 40.1,53.79 41.37,55.06 46.03,55.06 49.25,51.84 49.86,51.84 P4.10
ARD_SDA: length 39.3
  TOP w0.203: U2.5 29.7,40.76 29.71,40.76 29.99,40.76 31.47,42.24 31.47,45.67 29.69,47.44 29.69,48.21 29.98,48.5 U3.1 32.79,48.5 R3.2 33.92,48.17 34.79,47.3 R6.1 35.82,47.29 37.56,47.29 38.73,48.46 39.85,48.46 40.61,49.22 40.61,53.54 41.63,54.56 45.9,54.56 49.25,51.21 49.83,51.21 P4.9
BCOM: length 31.3
  TOP w0.203: P6.2 42.55,49.58 37.34,44.38 37.34,32.84 34.07,29.58 U1.G5
EXT_VIN: length 65.8
  TOP w0.635: v1(27.94,1.22) 36.32,1.22 39.47,4.37 JP1.4
  BOTTOM w0.635: P2.8 0.89,24.21 0.89,5.89 5.55,1.22 v1(27.94,1.22)
IOREF: length 73.6
  BOTTOM w0.635: IOSEL.1 39.78,5.11 37.97,3.3 10.73,3.3 5.46,8.57 5.46,38.18 P2.2
IOVDD: length 5.4
  TOP w0.508: v1(30.99,31.19) C8.1
  L2_GND w0.127: v2(28.29,28.78) 28.51,28.99
  L2_GND w0.152: 28.51,28.99 28.51,30.37
  L2_GND w0.381: 28.51,30.37 29.34,31.19
  L2_GND w0.508: 29.34,31.19 v1(30.99,31.19)
  vias: v1(22.45,47.57) v1(23.34,47.57) v1(24.23,47.57) v1(24.99,52.52) v1(24.99,46.3) v1(24.99,45.41) v1(24.99,44.52) v1(26.26,52.52) v1(33.12,52.14) v1(33.12,45.54)
LD1A_CAT: length 55.3
  TOP w0.203: P7.2 10.26,49.58 12.07,51.39 Q1.3 15.49,51.39 16.38,50.5 v1(18.41,50.5)
  BOTTOM w0.203: P10.5 18.41,7.92 v1(18.41,50.5)
LD1B_CAT: length 6.9
  TOP w0.203: P7.10 9.43,31.07 Q5.3
LD2A_CAT: length 6.9
  TOP w0.203: Q2.3 9.43,46.31 P7.4
LD2B_CAT: length 6.9
  TOP w0.203: P7.12 9.43,25.99 Q6.3
LD3A_CAT: length 6.9
  TOP w0.203: P7.6 9.43,41.23 Q3.3
LD3B_CAT: length 6.9
  TOP w0.203: Q7.3 9.43,20.91 P7.14
LD4A_CAT: length 6.9
  TOP w0.203: P7.8 9.43,36.15 Q4.3
LD4B_CAT: length 6.9
  TOP w0.203: P7.16 9.43,15.83 Q8.3
LED1A: length 33.4
  TOP w0.203: P7.3 8.41,47.83 16,47.83 16.48,48.31 P9.2 17.43,48.31 21.08,44.66 21.08,35 26.51,29.58 U1.A5
LED1B: length 20.9
  TOP w0.203: P7.11 8.41,27.51 16,27.51 16.48,27.99 P11.2 17.01,28 v1(19.95,28)
  L2_GND w0.127: v2(27.49,29.17) 27.49,29.17 27.3,28.98 25.5,28.98
  L2_GND w0.203: v1(19.95,28) 20.93,28.98 25.5,28.98
LED2A: length 29.5
  TOP w0.203: U1.A4 25.13,29.17 19.81,34.5 19.81,40.85 17.43,43.23 P13.2 16.48,43.23 16,42.75 8.41,42.75 P7.5
LED2B: length 25
  TOP w0.203: v1(21.34,28.01) 20.45,27.12 20.45,23.34 20.01,22.91 P15.2 16.48,22.91 16,22.43 8.41,22.43 P7.13
  L2_GND w0.127: 24.28,28.58 27.3,28.58 27.49,28.77 v2(27.49,28.78)
  L2_GND w0.203: v1(21.34,28.01) 23.72,28.01 24.28,28.58
LED3A: length 25.7
  TOP w0.203: U1.A3 23.75,28.78 18.54,33.99 18.54,37.04 17.43,38.15 P17.2 16.48,38.15 16,37.67 8.41,37.67 P7.7
LED3B: length 28.8
  TOP w0.203: P7.15 8.41,17.35 16,17.35 16.48,17.83 P19.2 19.61,17.83 21.46,19.69 v1(21.46,26.49)
  L2_GND w0.127: v2(27.49,28.37) 27.3,28.18 24.65,28.18
  L2_GND w0.203: 24.65,28.18 23.85,27.38 22.35,27.38 v1(21.46,26.49)
LED4A: length 21.9
  TOP w0.203: U1.A2 22.25,28.37 17.56,33.07 P22.2 16.48,33.07 16,32.59 8.41,32.59 P7.9
LED4B: length 33.1
  TOP w0.203: U1.A1 26.88,27.76 23.59,27.76 22.83,27 22.83,15.44 20.14,12.75 P24.2 16.48,12.75 15.87,12.14 v1(15.21,12.14)
  BOTTOM w0.203: P7.17 11.18,11.48 11.83,12.14 v1(15.21,12.14)
MISO: length 4.6
  TOP w0.203: JP2.1 30.07,9.68 30.43,9.32 P3.1
MOSI: length 7.5
  TOP w0.203: P3.4 26.64,6.65 JP4.1
PD1A: length 53.4
  L2_GND w0.127: 30.54,28.97 29.3,28.97 v2(29.09,29.17)
  L2_GND w0.203: v1(37.85,26.24) 35.43,26.24 32.7,28.97 30.54,28.97
  BOTTOM w0.203: P6.13 43.38,21.64 38.78,26.24 v1(37.85,26.24) 33.66,26.24 33.27,25.86 33.27,19.64 31.92,18.29 22.48,18.29 21.56,17.37 P10.1
PD1B: length 29.9
  TOP w0.203: P6.3 42.55,47.04 38.61,43.11 38.61,32.46 35.32,29.17 U1.G4
PD2A: length 20.6
  L2_GND w0.127: v2(29.09,28.78) 29.28,28.59 30.54,28.59
  L2_GND w0.203: v1(35.31,25.61) 32.32,28.59 30.54,28.59
  BOTTOM w0.203: v1(35.31,25.61) 37.87,25.61 44.35,19.13 45.69,19.13 P6.14
PD2B: length 28.5
  TOP w0.203: P6.4 42.55,44.5 39.88,41.84 39.88,32.08 36.57,28.78 U1.G3
PD3A: length 21.5
  L2_GND w0.127: v2(29.09,28.37) 29.33,28.14 30.58,28.14
  L2_GND w0.203: v1(36.32,24.46) 35.56,24.46 31.88,28.14 30.58,28.14
  BOTTOM w0.203: v1(36.32,24.46) 37.82,24.46 P6.15
PD3B: length 27
  TOP w0.203: U1.G2 37.82,28.37 41.15,31.7 41.15,40.57 42.55,41.96 P6.5
PD4A: length 23.4
  TOP w0.203: U1.F1 29.09,27.72 29.36,27.46 31.55,27.46 v1(34.54,24.46)
  BOTTOM w0.203: P6.16 43.28,16.46 43.28,17.98 37.82,23.44 35.56,23.44 v1(34.54,24.46)
PD4B: length 25.1
  TOP w0.203: P6.6 43.54,39.42 42.42,38.31 42.42,31.32 39.07,27.98 U1.G1
RESET: length 72.6
  TOP w0.203: P3.5 23.59,6.18 23.59,3.12 21.69,1.22 6.44,1.22 4.29,3.38 4.29,36.78 2.54,38.53 P2.3 4.29,40.31 4.29,45.08 S1.2
SCK: length 4.7
  TOP w0.203: P3.3 27.89,9.27 28.29,9.68 JP3.1
SPIMISO/I2CSCL: length 46.1
  TOP w0.203: R8.2 34.65,40.49 34.16,40.97 33.07,40.97 v1(32.65,40.55) ; U1.C1 27.89,27.36 27.02,26.49 v1(24.74,26.49) ; R7.2 37.2,49.58 v1(37.44,49.35)
  BOTTOM w0.203: v1(24.74,26.49) 24.45,26.78 24.45,39.54 25.88,40.97 32.23,40.97 v1(32.65,40.55) 33.06,40.97 34.14,40.97 34.71,41.54 34.71,43.19 35.66,44.14 38.58,44.14 39.34,44.9 39.34,48.46 38.71,49.1 37.69,49.1 v1(37.44,49.35)
SPISCK/I2CSDA: length 46.1
  TOP w0.203: R9.2 34.65,42.09 34.16,41.61 33.06,41.61 v1(32.65,42.02) ; v1(37.44,48.33) 37.21,48.11 R6.2
  L2_GND w0.127: v2(27.89,28.37) 27.3,27.78 25.01,27.78
  L2_GND w0.203: v1(23.72,26.49) 25.01,27.78
  BOTTOM w0.203: v1(23.72,26.49) 24,26.77 24,39.98 25.63,41.6 32.23,41.6 v1(32.65,42.02) 33.06,41.6 34.01,41.6 34.2,41.79 34.2,43.44 35.41,44.65 38.33,44.65 38.83,45.16 38.83,48.33 38.58,48.59 37.69,48.59 v1(37.44,48.33)
UNNAMED_2_ADPD4100_I288_VREF: length 2.7
  TOP w0.203: 28.83,30.69 28.69,30.55 U1.E5
  TOP w0.305: 29.34,31.19 28.83,30.69
  TOP w0.508: C5.1 29.34,31.19
UNNAMED_2_ADT75_I175_OS: length 28.1
  TOP w0.203: DS3.C 28.03,54.94 28.89,54.09 R5.2 28.89,50.4 29.49,49.8 U3.3
UNNAMED_2_CAP_I46_N1: length 2.2
  TOP w0.381: U4.4 31.57,35.83 C3.1
UNNAMED_2_CN6PODDEVEN_I283_N2: length 9.9
  TOP w0.203: D1.A 13.63,2.49 18.9,2.49 21.56,5.15 P10.2
UNNAMED_2_CN6PODDEVEN_I283_N4: length 10.8
  TOP w0.203: P10.4 20.29,5.15 18.9,3.76 12.29,3.76 12.03,3.5 D1.C
UNNAMED_2_CN6PODDEVEN_I283_N6: length 6.5
  TOP w0.203: P10.6 19.02,5.15 18.64,4.77 DS2.C
UNNAMED_2_CN8PA_I159_N3: length 8.2
  TOP w0.203: P5.3 49.86,13.16 49.45,12.75 JP8.2
UNNAMED_2_CN8PA_I159_N4: length 8.2
  TOP w0.203: P5.4 49.86,15.7 49.45,15.29 JP7.2
UNNAMED_2_CN8PA_I159_N5: length 8.2
  TOP w0.203: P5.5 49.86,18.24 49.45,17.83 JP6.2
UNNAMED_2_CN8PA_I159_N6: length 8.2
  TOP w0.203: JP5.2 49.45,20.37 49.86,20.78 P5.6
UNNAMED_2_DIOLED_I100_P: length 3.3
  TOP w0.203: DS1.A 5.18,53.31 5.18,53.01 5.18,53.01 R1.1
UNNAMED_2_DIOLED_I182_P: length 18.8
  TOP w0.203: R4.1 22.36,53.5 21.69,54.18 5.72,54.18 5.59,54.31 5.59,54.65 DS3.A
UNNAMED_2_NC2P_I236_N1: length 2.2
  TOP w0.203: Q8.2 14.81,13.56 P24.1
UNNAMED_2_NC2P_I275_N1: length 2.2
  TOP w0.203: Q1.2 14.81,49.12 P9.1
UNNAMED_2_NC2P_I276_N1: length 2.2
  TOP w0.203: P13.1 14.81,44.04 Q2.2
UNNAMED_2_NC2P_I277_N1: length 2.2
  TOP w0.203: Q3.2 14.81,38.96 P17.1
UNNAMED_2_NC2P_I278_N1: length 2.2
  TOP w0.203: Q4.2 14.81,33.88 P22.1
UNNAMED_2_NC2P_I279_N1: length 2.2
  TOP w0.203: P11.1 14.81,28.8 Q5.2
UNNAMED_2_NC2P_I280_N1: length 2.2
  TOP w0.203: Q6.2 14.81,23.72 P15.1
UNNAMED_2_NC2P_I281_N1: length 2.2
  TOP w0.203: P19.1 14.81,18.64 Q7.2

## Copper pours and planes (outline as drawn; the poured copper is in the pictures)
1V8D on TOP: 28.7,26.37 27.05,24.72 27.05,22.18 29.21,22.18 29.34,22.3 29.34,25.73
1V8D on TOP: 33.88,38.81 31.09,38.81 30.45,38.17 28.8,38.17 28.67,38.05 28.67,37.41 28.8,37.28 30.45,37.28 30.71,37.03 33.88,37.03 34.01,37.16 34.01,38.68
1V8D on L3_PWR: 0.51,55.81 52.83,55.81 52.83,3.05 40.18,3.05 37.64,0.51 5.29,0.51 2.75,3.05 0.51,3.05
3V_ARD on TOP: 24.74,34.49 24.86,34.36 26.13,34.36 27.15,35.38 27.91,35.38 28.04,35.51 28.04,36.01 27.91,36.14 24.86,36.14 24.74,36.01
3V_ARD on TOP: 24.74,39.06 24.86,39.19 26.13,39.19 27.15,38.17 27.91,38.17 28.04,38.05 28.04,37.54 27.91,37.41 24.86,37.41 24.74,37.54
3V_ARD on L3_PWR: 0.99,55.57 21.56,55.57 21.56,40.71 22.45,39.82 26.01,39.82 26.51,39.32 26.52,34.36 26.51,33.73 20.67,33.73 19.78,34.62 19.78,53.29 18.89,54.18 14.7,54.18 14.58,54.05 11.02,50.49 8.1,50.49 7.59,49.98 7.46,11.25 9.12,9.6 35.79,9.6 37.95,11.76 39.09,11.76 39.34,11.5 39.34,3.12 37.31,1.09 5.31,1.09 2.89,3.5 0.99,3.5
DGND on TOP: 0.51,55.81 52.83,55.81 52.83,3.76 52.83,3.05 40.18,3.05 37.64,0.51 5.29,0.51 2.75,3.05 0.51,3.05
DGND on BOTTOM: 0.51,55.81 52.83,55.81 52.83,3.05 40.18,3.05 37.64,0.51 5.29,0.51 2.75,3.05 0.51,3.05 0.51,24.75
DGND on L2_GND: 0.51,55.81 52.83,55.81 52.83,3.05 40.18,3.05 37.64,0.51 5.29,0.51 2.75,3.05 0.51,3.05
IOVDD on TOP: 32.36,46.81 32.48,46.94 33.75,46.94 33.88,46.81 33.88,45.41 33.75,45.29 32.48,45.29 32.36,45.41
IOVDD on TOP: 23.47,53.03 23.59,53.16 27.66,53.16 27.79,53.03 27.79,52.02 27.66,51.89 23.59,51.89 23.47,52.02
IOVDD on TOP: 32.36,52.27 32.48,52.4 33.75,52.4 33.88,52.27 33.88,50.87 33.75,50.75 32.48,50.75 32.36,50.87
IOVDD on TOP: 21.69,48.92 21.82,49.05 24.61,49.05 24.93,48.73 26.77,48.73 26.9,48.61 26.9,47.59 26.64,47.34 21.82,47.34 21.69,47.46
IOVDD on TOP: 24.49,46.83 26.64,46.83 26.64,43.78 27.03,43.4 29.18,43.4 29.31,43.27 29.31,42.64 29.18,42.49 24.93,42.51 24.49,42.95
IOVDD on L3_PWR: 26.9,39.44 26.9,33.73 28.67,33.73 29.69,32.71 29.69,30.93 29.94,30.68 31.59,30.68 31.85,30.93 31.85,36.52 30.71,37.67 30.71,43.89 31.47,44.65 47.47,44.65 49.12,43 49.12,4.39 48.74,4.01 46.71,4.01 46.33,4.39 46.33,5.53 45.31,6.55 39.72,6.55 39.72,3.12 52.55,3.12 52.55,55.57 22.07,55.57 22.07,40.84 22.7,40.21 26.13,40.21

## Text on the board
Ref Des/Silkscreen Bottom: SECONDARY SIDE | 08-066249  REV D Z | ICSP
User.Comments: 6.   INSTALL JUMPER SHUNT (M028265) ON LOCATIONS BELOW: | 4.   RoHS COMPLIANCE: ASSEMBLY VENDOR SHOULD ASSURE COMPLIANCE | 5.   BOARDS TO BE SHIPPED SINGULATED AFTER ASSEMBLY PROCCESS.. | 7.   INSTALL JUMPER SHUNT (M036050) ON LOCATIONS BELOW: | SMOOTHEN EDGES AND FREE FROM BURS AFTER DEPANELIZATION PROCESS. | A. P10 (PIN 1 & 2) | B. P10 (PIN 3 & 4) | C. P10 (PIN 5 & 6) | WITH LEAD-FREE AND RoHS PCB ASSEMBLY STANDARDS (EU RoHS | DIRECTIVE 2002/95/EC). | A. IOSEL (PIN 1 & 2) | 10.   E050393 (SSW-118-01-T-S-LL) ARE TO SHIP AND NO NEED TO INSTALL. | 11.   DO NOT TRIM EXCESS PINS OF P1, P2, P3, P4 & P5. | 8.   ADD SOLDER BLOB FOR THE FOLLOWING LOCATIONS: | 9.   ADD SOLDER BLOB FOR THE FOLLOWING LOCATIONS: | A. P9 | B. P11 | C. P13 | D. P15 | ADPD4100 | DEFAULT | FOR | R8 | R9 | E. P17 | F. P19 | G. P22 | H. P24 | ADPD4101 | R6 | R7 | I. JP1 (PINS 2 & 3)
Ref Des/Assembly Top: 5 | 6 | 2 | 3
Ref Des/Silkscreen Top: 08-066249  REV C Z | EVAL-ADPD4100-ARDZ | PRIMARY SIDE | ICSP | BCOM | PD1B | PD2B | PD3B | PD4B | ACOM | PD1A | PD2A | PD3A | PD4A | GND | I03 | IO2 | IO1 | IO0 | VCC | L2A | 3AC | 1AC | L1A | 2AC | L3A | 4AC | L4A | 1BC | L1B | 2BC | L2B | 3BC | L3B | 4BC | L4B | 3
XSECTION_CHART: *  SURFACE | *  SOLDERMASK_TOP MASK | L1 TOP CONDUCTOR | *  DIELECTRIC | L2 L2_GND PLANE | L3 L3_PWR PLANE | L4 BOTTOM CONDUCTOR | *  SOLDERMASK_BOTTOM MASK | DESIGN CROSS SECTION CHART | ___________________________ | TOTAL THICKNESS 62 MIL | 1-4 | 1-2
PAGE_OUTLINE: 12APR21 | B | C | D | AS PER ECR-105120 | AS PER ECR-106842 | AS PER ECR-107571 | 17NOV21 | 28JAN22 | 08MAR22 | A.CATAPANG | CUSTOMER EVALUATION Z
DIMENSION: (REF) | DIA MAX
BODY_CENTER: L4 SECONDARY | 08-      -02
User.13: 15.    LASER VIAS TO BE COPPER FILLED (PLATED SHUT) AND PLANARIZED. | 16.    BOARDS TO BE SHIPPED IN ARRAY AND KEEP INTACT. | PANEL TO BE SUBJECTED TO CUSTOMER'S APPROVAL. | PANELED SOLDER PASTE STENCIL SHOULD BE SENT TO THE CUSTOMER.
User.15: BELOW THIS LINE | EXTEND BOARD | IF REQUIRED
User.16: *     Install shunt M036050 to JP1 pins 4,6. | *     Install shunt M036050 to IOSEL pins 1,2. | *     Install shunt M036050 | to JP1 pins 3,5.
User.17: L3 PWR | 08-      -08
User.20: (SPI) | (I2C)
User.21: A1
User.23: L2 GND | 08-      -07
User.24: DIA MAX/SEE NOTE 15 | BVIA 1-2
User.25: COMPONENT KEEPOUT AREA | COMPONENTS GREATER THAN 1.5MM
User.40: PER ECR-094468 | B | 28MAY20 | PD
User.42: PAGE 1 OF 5 | TOP SIDE VIEW | VIEW OF SILKSCREEN, PINS, VIAS, | ETCH AND REFERENCE INFORMATION. | TEMPLATE NOTES. | 01.COMPONENTS ARE PLACED ON THIS SIDE. | 02.CONNECTORS P1,P2.P4 & P5 ARE PLACED | ON THIS SIDE OF THE BOARD. | 03.IF THE BOARD NEEDS TO BE INCREASED | IT CAN BE INCREASED IN THE DIRECTION | OF THE ARROWS. | 04.THE BOARD IS SET-UP AS A 4 LAYER | BOARD. MAKE SURE ANY SUBSEQUENT CHANGES, | MANUAL OR AUTOMATIC, DO NOT RESULT IN | ANY UNINTENDED CONSEQUENCES. | 05.THE EXISTING ROUTING CAN BE ALTERED AS | IS ROUTED TO CLOSE THE NETS ON THE | TEMPLATE BOARD.
User.43: PAGE 2 OF 5 | BOTTTOM SIDE VIEW | VIEW OF SILKSCREEN, PINS, VIAS, | ETCH AND REFERENCE INFORMATION. | TEMPLATE NOTES. | 01.COMPONENTS ARE PLACED ON THIS SIDE. | 02.CONNECTORS P3 IS PLACED ON THIS SIDE. THE | OTHER CONNECTORS ARE SOLDERED THIS SIDE. | 03.THE TEMPLATE IS VIEWED LOOKING FROM THE | TOP SIDE OF THE BOARD. THE RESULT IS | THAT TEXT IS MIRRORED. | 04.THE BOARD IS SET-UP AS A 4 LAYER | BOARD. MAKE SURE ANY SUBSEQUENT CHANGES, | MANUAL OR AUTOMATIC, DO NOT RESULT IN | ANY UNINTENDED CONSEQUENCES.
User.44: PAGE 3 OF 5 | PCB FAB SHEET 1 | NCDRILL LEGEND, APPROPRIATE | DETAILS AND OUTLINE DIMENSION NOTES. | 01. EACH TIME THE NC DRILL LEGEND | IS RUN, THE HOLE CHART MUST BE | CHECKED TO ASSURE THE TOLERANCES | & NOTES CORRESPOND TO THE RIGHT | PADSTACKS.
User.45: 1 | FABRICATION | 09-012345-01 | A | TEMPLATE REVISION HISTORY | TEMPLATE BOARDS FOR EVAL PROVIDE INFORMATION IN THE | 5-VIEW "PDF FORMAT" FOR EVAL ENGINEERING | REFERENCE; ALONG WITH EMBEDDED ALLEGRO | PROPERTIES FOR PCB DESIGN USE. | THEY MAINTAIN A SEPARATE TITLE BLOCK AND PART | NUMBER FOR REVISION TRACKING, INDEPENDENT OF | THE ACTUAL MANUFACTURED DUT-SPECIFIC BOARD | DESIGN. | TEMPLATE BOARDS DISPLAY AS "FILE VIEWS", AND | DUT-SPECIFIC APPLICATION BOARDS ARE | MANUFACTURED FROM ARTWORK "FILM VIEWS"AND NC | DATA. | AND TITLE BLOCK CONTENT IS TRACKING THE | MANUFACTURED BOARD PART NUMBER AND REV, | AND NOT THE TEMPLATE BOARD PART NUMBER AND | REV. | PAGE 5 OF 5 | MAKE SURE THE DUT-SPECIFIC BOARD INFORMATION | REV.A (20APR20) | 1. INITIAL RELEASE. | REV.B (28MAY20) PER ECR-094468 | 1. BRING FILES INTO TEMPLATE FORMAT. | PAGE 4 OF 5 | PCB FAB SHEET 2 | FABRICATION NOTES. ALTER DEPENDING ON THE | REQUIREMENTS OF THE DESIGN. | FIGURE | SIZE | 10.0 | 4.0 | 30.0 | 40.0 | 45.0 | PLATED | DRILL CHART: TOP to BOTTOM | DRILL CHART: TOP to L2_GND | ALL UNITS ARE IN MILS | QTY | 14 | 265 | 6 | 2 | 77 | TOLERANCE/NOTES
